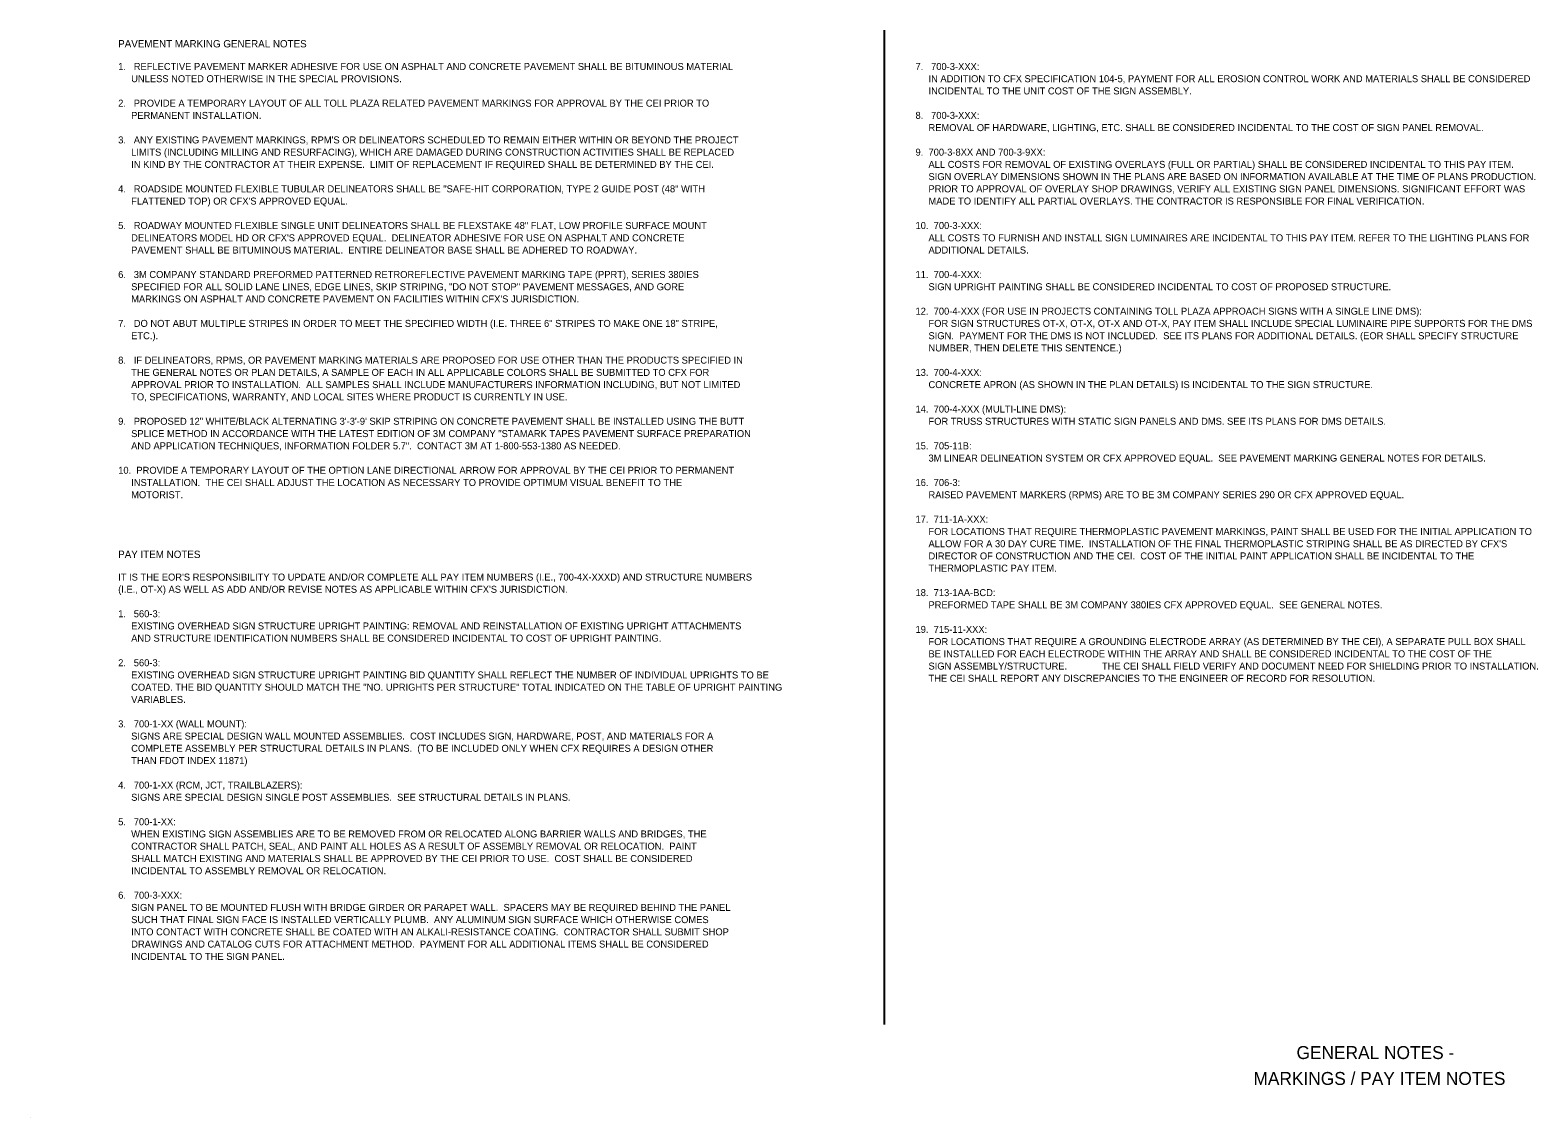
# Model space of a CAD drawing. Extents: x 2479959 to 2482822, y 3677554 to 3678604.
# Drawn here: x 2479959 to 2481415, y 3677554 to 3678604 of the extents above; entities that cross this region are included whole.
import ezdxf

# ---------------------------------------------------------------- set-up
doc = ezdxf.new("R2010")
doc.units = 0
for name, color, linetype in [('AdhocPoint_dp', 7, 'Continuous'), ('NonPlottingEle_dp', 7, 'Continuous'), ('TextLabel', 7, 'Continuous'), ('TextMisc', 7, 'Continuous')]:
    doc.layers.add(name, color=color, linetype=linetype)

msp = doc.modelspace()

# ---------------------------------------------------------------- linework, layer by layer
at = {"layer": 'AdhocPoint_dp'}
msp.add_line((2479959.3, 3677553.8), (2479959.3, 3677553.8), dxfattribs=at)
at = {"layer": 'NonPlottingEle_dp'}
msp.add_line((2480784.3, 3677643.8), (2480784.3, 3678603.8), dxfattribs=at)

# ---------------------------------------------------------------- texts
at = {"layer": 'TextLabel'}
for s, height, p in [('PAVEMENT MARKING GENERAL NOTES', 7.08, (2480044.3, 3678587.2)), ('1.   REFLECTIVE PAVEMENT MARKER ADHESIVE FOR USE ON ASPHALT AND CONCRETE PAVEMENT SHALL BE BITUMINOUS MATERIAL', 6.75, (2480044.3, 3678565.4)), ('7.   700-3-XXX:', 6.75, (2480814.3, 3678565.4)), ('     UNLESS NOTED OTHERWISE IN THE SPECIAL PROVISIONS.', 6.75, (2480044.3, 3678553.6)), ('     IN ADDITION TO CFX SPECIFICATION 104-5, PAYMENT FOR ALL EROSION CONTROL WORK AND MATERIALS SHALL BE CONSIDERED', 6.75, (2480814.3, 3678553.6)), ('     INCIDENTAL TO THE UNIT COST OF THE SIGN ASSEMBLY.', 6.75, (2480814.3, 3678541.8)), ('2.   PROVIDE A TEMPORARY LAYOUT OF ALL TOLL PLAZA RELATED PAVEMENT MARKINGS FOR APPROVAL BY THE CEI PRIOR TO', 6.75, (2480044.3, 3678530)), ('     PERMANENT INSTALLATION.', 6.75, (2480044.3, 3678518.2)), ('8.   700-3-XXX:', 6.75, (2480814.3, 3678518.2)), ('     REMOVAL OF HARDWARE, LIGHTING, ETC. SHALL BE CONSIDERED INCIDENTAL TO THE COST OF SIGN PANEL REMOVAL.', 6.75, (2480814.3, 3678506.4)), ("3.   ANY EXISTING PAVEMENT MARKINGS, RPM'S OR DELINEATORS SCHEDULED TO REMAIN EITHER WITHIN OR BEYOND THE PROJECT", 6.75, (2480044.3, 3678494.5)), ('     LIMITS (INCLUDING MILLING AND RESURFACING), WHICH ARE DAMAGED DURING CONSTRUCTION ACTIVITIES SHALL BE REPLACED', 6.75, (2480044.3, 3678482.7)), ('9.  700-3-8XX AND 700-3-9XX:', 6.75, (2480814.3, 3678482.7)), ('     IN KIND BY THE CONTRACTOR AT THEIR EXPENSE.  LIMIT OF REPLACEMENT IF REQUIRED SHALL BE DETERMINED BY THE CEI.', 6.75, (2480044.3, 3678470.9)), ('     ALL COSTS FOR REMOVAL OF EXISTING OVERLAYS (FULL OR PARTIAL) SHALL BE CONSIDERED INCIDENTAL TO THIS PAY ITEM. ', 6.75, (2480814.3, 3678470.9)), ('     SIGN OVERLAY DIMENSIONS SHOWN IN THE PLANS ARE BASED ON INFORMATION AVAILABLE AT THE TIME OF PLANS PRODUCTION.  ', 6.75, (2480814.3, 3678459.1)), ('4.   ROADSIDE MOUNTED FLEXIBLE TUBULAR DELINEATORS SHALL BE "SAFE-HIT CORPORATION, TYPE 2 GUIDE POST (48" WITH', 6.75, (2480044.3, 3678447.3)), ('     PRIOR TO APPROVAL OF OVERLAY SHOP DRAWINGS, VERIFY ALL EXISTING SIGN PANEL DIMENSIONS. SIGNIFICANT EFFORT WAS ', 6.75, (2480814.3, 3678447.3)), ("     FLATTENED TOP) OR CFX'S APPROVED EQUAL.", 6.75, (2480044.3, 3678435.5)), ('     MADE TO IDENTIFY ALL PARTIAL OVERLAYS. THE CONTRACTOR IS RESPONSIBLE FOR FINAL VERIFICATION. ', 6.75, (2480814.3, 3678435.5)), ('5.   ROADWAY MOUNTED FLEXIBLE SINGLE UNIT DELINEATORS SHALL BE FLEXSTAKE 48" FLAT, LOW PROFILE SURFACE MOUNT', 6.75, (2480044.3, 3678411.9)), ("     DELINEATORS MODEL HD OR CFX'S APPROVED EQUAL.  DELINEATOR ADHESIVE FOR USE ON ASPHALT AND CONCRETE", 6.75, (2480044.3, 3678400)), ('10.  700-3-XXX:', 6.75, (2480814.3, 3678411.9)), ('     ALL COSTS TO FURNISH AND INSTALL SIGN LUMINAIRES ARE INCIDENTAL TO THIS PAY ITEM. REFER TO THE LIGHTING PLANS FOR', 6.75, (2480814.3, 3678400)), ('     PAVEMENT SHALL BE BITUMINOUS MATERIAL.  ENTIRE DELINEATOR BASE SHALL BE ADHERED TO ROADWAY.', 6.75, (2480044.3, 3678388.2)), ('     ADDITIONAL DETAILS.', 6.75, (2480814.3, 3678388.2)), ('6.   3M COMPANY STANDARD PREFORMED PATTERNED RETROREFLECTIVE PAVEMENT MARKING TAPE (PPRT), SERIES 380IES ', 6.75, (2480044.3, 3678364.6)), ('11.  700-4-XXX:', 6.75, (2480814.3, 3678364.6)), ('     SPECIFIED FOR ALL SOLID LANE LINES, EDGE LINES, SKIP STRIPING, "DO NOT STOP" PAVEMENT MESSAGES, AND GORE', 6.75, (2480044.3, 3678352.8)), ('     SIGN UPRIGHT PAINTING SHALL BE CONSIDERED INCIDENTAL TO COST OF PROPOSED STRUCTURE.', 6.75, (2480814.3, 3678352.8)), ("     MARKINGS ON ASPHALT AND CONCRETE PAVEMENT ON FACILITIES WITHIN CFX'S JURISDICTION.", 6.75, (2480044.3, 3678341)), ('12.  700-4-XXX (FOR USE IN PROJECTS CONTAINING TOLL PLAZA APPROACH SIGNS WITH A SINGLE LINE DMS):', 6.75, (2480814.3, 3678329.2)), ('7.   DO NOT ABUT MULTIPLE STRIPES IN ORDER TO MEET THE SPECIFIED WIDTH (I.E. THREE 6" STRIPES TO MAKE ONE 18" STRIPE,', 6.75, (2480044.3, 3678317.4)), ('     FOR SIGN STRUCTURES OT-X, OT-X, OT-X AND OT-X, PAY ITEM SHALL INCLUDE SPECIAL LUMINAIRE PIPE SUPPORTS FOR THE DMS', 6.75, (2480814.3, 3678317.4)), ('     ETC.).', 6.75, (2480044.3, 3678305.5)), ('     SIGN.  PAYMENT FOR THE DMS IS NOT INCLUDED.  SEE ITS PLANS FOR ADDITIONAL DETAILS. (EOR SHALL SPECIFY STRUCTURE ', 6.75, (2480814.3, 3678305.5)), ('     NUMBER, THEN DELETE THIS SENTENCE.)', 6.75, (2480814.3, 3678293.7)), ('8.   IF DELINEATORS, RPMS, OR PAVEMENT MARKING MATERIALS ARE PROPOSED FOR USE OTHER THAN THE PRODUCTS SPECIFIED IN', 6.75, (2480044.3, 3678281.9)), ('     THE GENERAL NOTES OR PLAN DETAILS, A SAMPLE OF EACH IN ALL APPLICABLE COLORS SHALL BE SUBMITTED TO CFX FOR', 6.75, (2480044.3, 3678270.1)), ('13.  700-4-XXX:', 6.75, (2480814.3, 3678270.1)), ('     APPROVAL PRIOR TO INSTALLATION.  ALL SAMPLES SHALL INCLUDE MANUFACTURERS INFORMATION INCLUDING, BUT NOT LIMITED', 6.75, (2480044.3, 3678258.3)), ('     CONCRETE APRON (AS SHOWN IN THE PLAN DETAILS) IS INCIDENTAL TO THE SIGN STRUCTURE. ', 6.75, (2480814.3, 3678258.3)), ('     TO, SPECIFICATIONS, WARRANTY, AND LOCAL SITES WHERE PRODUCT IS CURRENTLY IN USE.', 6.75, (2480044.3, 3678246.5)), ('14.  700-4-XXX (MULTI-LINE DMS):', 6.75, (2480814.3, 3678234.7)), ('9.   PROPOSED 12" WHITE/BLACK ALTERNATING 3\'-3\'-9\' SKIP STRIPING ON CONCRETE PAVEMENT SHALL BE INSTALLED USING THE BUTT', 6.75, (2480044.3, 3678222.9)), ('     SPLICE METHOD IN ACCORDANCE WITH THE LATEST EDITION OF 3M COMPANY "STAMARK TAPES PAVEMENT SURFACE PREPARATION', 6.75, (2480044.3, 3678211)), ('     FOR TRUSS STRUCTURES WITH STATIC SIGN PANELS AND DMS. SEE ITS PLANS FOR DMS DETAILS.', 6.75, (2480814.3, 3678222.9)), ('     AND APPLICATION TECHNIQUES, INFORMATION FOLDER 5.7".  CONTACT 3M AT 1-800-553-1380 AS NEEDED.', 6.75, (2480044.3, 3678199.2)), ('15.  705-11B:', 6.75, (2480814.3, 3678199.2)), ('     3M LINEAR DELINEATION SYSTEM OR CFX APPROVED EQUAL.  SEE PAVEMENT MARKING GENERAL NOTES FOR DETAILS.', 6.75, (2480814.3, 3678187.4)), ('10.  PROVIDE A TEMPORARY LAYOUT OF THE OPTION LANE DIRECTIONAL ARROW FOR APPROVAL BY THE CEI PRIOR TO PERMANENT', 6.75, (2480044.3, 3678175.6)), ('     INSTALLATION.  THE CEI SHALL ADJUST THE LOCATION AS NECESSARY TO PROVIDE OPTIMUM VISUAL BENEFIT TO THE', 6.75, (2480044.3, 3678163.8)), ('16.  706-3:', 6.75, (2480814.3, 3678163.8)), ('     MOTORIST.', 6.75, (2480044.3, 3678152)), ('     RAISED PAVEMENT MARKERS (RPMS) ARE TO BE 3M COMPANY SERIES 290 OR CFX APPROVED EQUAL.', 6.75, (2480814.3, 3678152)), ('17.  711-1A-XXX:', 6.75, (2480814.3, 3678128.4)), ('     FOR LOCATIONS THAT REQUIRE THERMOPLASTIC PAVEMENT MARKINGS, PAINT SHALL BE USED FOR THE INITIAL APPLICATION TO', 6.75, (2480814.3, 3678116.5)), ('PAY ITEM NOTES', 7.08, (2480044.3, 3678094.3)), ("     ALLOW FOR A 30 DAY CURE TIME.  INSTALLATION OF THE FINAL THERMOPLASTIC STRIPING SHALL BE AS DIRECTED BY CFX'S", 6.75, (2480814.3, 3678104.7)), ('     THERMOPLASTIC PAY ITEM.', 6.75, (2480814.3, 3678081.1)), ('     DIRECTOR OF CONSTRUCTION AND THE CEI.  COST OF THE INITIAL PAINT APPLICATION SHALL BE INCIDENTAL TO THE', 6.75, (2480814.3, 3678092.9)), ("IT IS THE EOR'S RESPONSIBILITY TO UPDATE AND/OR COMPLETE ALL PAY ITEM NUMBERS (I.E., 700-4X-XXXD) AND STRUCTURE NUMBERS", 6.75, (2480044.3, 3678072.5)), ("(I.E., OT-X) AS WELL AS ADD AND/OR REVISE NOTES AS APPLICABLE WITHIN CFX'S JURISDICTION.", 6.75, (2480044.3, 3678060.7)), ('18.  713-1AA-BCD:', 6.75, (2480814.3, 3678057.5)), ('1.   560-3:', 6.75, (2480044.3, 3678037.1)), ('     PREFORMED TAPE SHALL BE 3M COMPANY 380IES CFX APPROVED EQUAL.  SEE GENERAL NOTES.', 6.75, (2480814.3, 3678045.7)), ('     EXISTING OVERHEAD SIGN STRUCTURE UPRIGHT PAINTING: REMOVAL AND REINSTALLATION OF EXISTING UPRIGHT ATTACHMENTS', 6.75, (2480044.3, 3678025.3)), ('19.  715-11-XXX:', 6.75, (2480814.3, 3678022)), ('     AND STRUCTURE IDENTIFICATION NUMBERS SHALL BE CONSIDERED INCIDENTAL TO COST OF UPRIGHT PAINTING.', 6.75, (2480044.3, 3678013.5)), ('     FOR LOCATIONS THAT REQUIRE A GROUNDING ELECTRODE ARRAY (AS DETERMINED BY THE CEI), A SEPARATE PULL BOX SHALL ', 6.75, (2480814.3, 3678010.2)), ('     BE INSTALLED FOR EACH ELECTRODE WITHIN THE ARRAY AND SHALL BE CONSIDERED INCIDENTAL TO THE COST OF THE ', 6.75, (2480814.3, 3677998.4)), ('2.   560-3:', 6.75, (2480044.3, 3677989.8)), ('     EXISTING OVERHEAD SIGN STRUCTURE UPRIGHT PAINTING BID QUANTITY SHALL REFLECT THE NUMBER OF INDIVIDUAL UPRIGHTS TO BE', 6.75, (2480044.3, 3677978)), ('     SIGN ASSEMBLY/STRUCTURE.  ', 6.75, (2480814.3, 3677986.6)), ('THE CEI SHALL FIELD VERIFY AND DOCUMENT NEED FOR SHIELDING PRIOR TO INSTALLATION.  ', 6.75, (2480994.4, 3677986.6)), ('     COATED. THE BID QUANTITY SHOULD MATCH THE "NO. UPRIGHTS PER STRUCTURE" TOTAL INDICATED ON THE TABLE OF UPRIGHT PAINTING', 6.75, (2480044.3, 3677966.2)), ('     THE CEI SHALL REPORT ANY DISCREPANCIES TO THE ENGINEER OF RECORD FOR RESOLUTION.', 6.75, (2480814.3, 3677974.8)), ('     VARIABLES.', 6.75, (2480044.3, 3677954.4)), ('3.   700-1-XX (WALL MOUNT):', 6.75, (2480044.3, 3677930.8)), ('     SIGNS ARE SPECIAL DESIGN WALL MOUNTED ASSEMBLIES.  COST INCLUDES SIGN, HARDWARE, POST, AND MATERIALS FOR A', 6.75, (2480044.3, 3677919)), ('     COMPLETE ASSEMBLY PER STRUCTURAL DETAILS IN PLANS.  (TO BE INCLUDED ONLY WHEN CFX REQUIRES A DESIGN OTHER', 6.75, (2480044.3, 3677907.2)), ('     THAN FDOT INDEX 11871)', 6.75, (2480044.3, 3677895.3)), ('4.   700-1-XX (RCM, JCT, TRAILBLAZERS):', 6.75, (2480044.3, 3677871.7)), ('     SIGNS ARE SPECIAL DESIGN SINGLE POST ASSEMBLIES.  SEE STRUCTURAL DETAILS IN PLANS.', 6.75, (2480044.3, 3677859.9)), ('5.   700-1-XX:', 6.75, (2480044.3, 3677836.3)), ('     WHEN EXISTING SIGN ASSEMBLIES ARE TO BE REMOVED FROM OR RELOCATED ALONG BARRIER WALLS AND BRIDGES, THE', 6.75, (2480044.3, 3677824.5)), ('     CONTRACTOR SHALL PATCH, SEAL, AND PAINT ALL HOLES AS A RESULT OF ASSEMBLY REMOVAL OR RELOCATION.  PAINT', 6.75, (2480044.3, 3677812.7)), ('     SHALL MATCH EXISTING AND MATERIALS SHALL BE APPROVED BY THE CEI PRIOR TO USE.  COST SHALL BE CONSIDERED', 6.75, (2480044.3, 3677800.8)), ('     INCIDENTAL TO ASSEMBLY REMOVAL OR RELOCATION.', 6.75, (2480044.3, 3677789)), ('6.   700-3-XXX:', 6.75, (2480044.3, 3677765.4)), ('     SIGN PANEL TO BE MOUNTED FLUSH WITH BRIDGE GIRDER OR PARAPET WALL.  SPACERS MAY BE REQUIRED BEHIND THE PANEL', 6.75, (2480044.3, 3677753.6)), ('     SUCH THAT FINAL SIGN FACE IS INSTALLED VERTICALLY PLUMB.  ANY ALUMINUM SIGN SURFACE WHICH OTHERWISE COMES', 6.75, (2480044.3, 3677741.8)), ('     DRAWINGS AND CATALOG CUTS FOR ATTACHMENT METHOD.  PAYMENT FOR ALL ADDITIONAL ITEMS SHALL BE CONSIDERED', 6.75, (2480044.3, 3677718.2)), ('     INTO CONTACT WITH CONCRETE SHALL BE COATED WITH AN ALKALI-RESISTANCE COATING.  CONTRACTOR SHALL SUBMIT SHOP', 6.75, (2480044.3, 3677730)), ('     INCIDENTAL TO THE SIGN PANEL.', 6.75, (2480044.3, 3677706.3))]:
    msp.add_text(s, height=height, dxfattribs=at).set_placement(p)
at = {"layer": 'TextMisc'}
for s, p in [('    GENERAL NOTES -     ', (2481163.7, 3677610.6)), ('MARKINGS / PAY ITEM NOTES', (2481140.7, 3677585.6))]:
    msp.add_text(s, height=12.5, rotation=360, dxfattribs=at).set_placement(p)

doc.saveas('drawing.dxf')
